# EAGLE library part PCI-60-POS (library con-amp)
PCI-SLOT 60 Dual Position 0.05 Series Standard Edge Source: http://catalog.tycoelectronics.com .. ENG_CD_145167_F.pdf
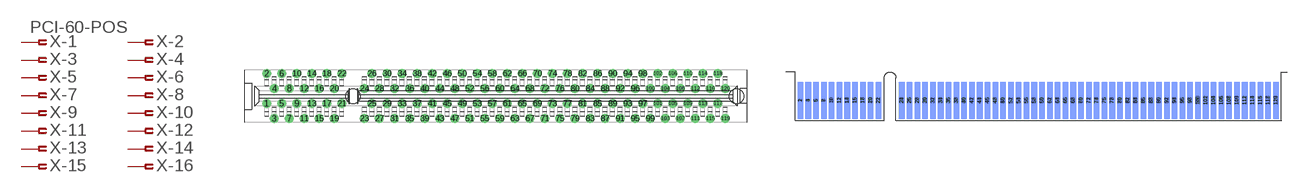
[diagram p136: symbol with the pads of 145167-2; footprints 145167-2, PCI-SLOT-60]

Designator prefix X; gates -1=PIN-FV -2=PIN-F -3=PIN-F -4=PIN-F -5=PIN-F -6=PIN-F -7=PIN-F -8=PIN-F -9=PIN-F -10=PIN-F -11=PIN-F -12=PIN-F -13=PIN-F -14=PIN-F -15=PIN-F -16=PIN-F -17=PIN-F -18=PIN-F -19=PIN-F -20=PIN-F -21=PIN-F -22=PIN-F -23=PIN-F -24=PIN-F -25=PIN-F -26=PIN-F -27=PIN-F -28=PIN-F -29=PIN-F -30=PIN-F -31=PIN-F -32=PIN-F -33=PIN-F -34=PIN-F -35=PIN-F -36=PIN-F -37=PIN-F -38=PIN-F -39=PIN-F -40=PIN-F -41=PIN-F -42=PIN-F -43=PIN-F -44=PIN-F -45=PIN-F -46=PIN-F -47=PIN-F -48=PIN-F -49=PIN-F -50=PIN-F -51=PIN-F -52=PIN-F -53=PIN-F -54=PIN-F -55=PIN-F -56=PIN-F -57=PIN-F -58=PIN-F -59=PIN-F -60=PIN-F -61=PIN-F -62=PIN-F -63=PIN-F -64=PIN-F -65=PIN-F -66=PIN-F -67=PIN-F -68=PIN-F -69=PIN-F -70=PIN-F -71=PIN-F -72=PIN-F -73=PIN-F -74=PIN-F -75=PIN-F -76=PIN-F -77=PIN-F -78=PIN-F -79=PIN-F -80=PIN-F -81=PIN-F -82=PIN-F -83=PIN-F -84=PIN-F -85=PIN-F -86=PIN-F -87=PIN-F -88=PIN-F -89=PIN-F -90=PIN-F -91=PIN-F -92=PIN-F -93=PIN-F -94=PIN-F -95=PIN-F -96=PIN-F -97=PIN-F -98=PIN-F -99=PIN-F -100=PIN-F -101=PIN-F -102=PIN-F -103=PIN-F -104=PIN-F -105=PIN-F -106=PIN-F -107=PIN-F -108=PIN-F -109=PIN-F -110=PIN-F -111=PIN-F -112=PIN-F -113=PIN-F -114=PIN-F -115=PIN-F -116=PIN-F -117=PIN-F -118=PIN-F -119=PIN-F -120=PIN-F

## PCI-60-POS-145167 (MPN: 145167-2; OC_FARNELL: unknown; OC_NEWARK: 17R3225)  [145167-2]
1  -1:1  pas
2  -2:1  pas
3  -3:1  pas
4  -4:1  pas
5  -5:1  pas
6  -6:1  pas
7  -7:1  pas
8  -8:1  pas
9  -9:1  pas
10  -10:1  pas
11  -11:1  pas
12  -12:1  pas
13  -13:1  pas
14  -14:1  pas
15  -15:1  pas
16  -16:1  pas
17  -17:1  pas
18  -18:1  pas
19  -19:1  pas
20  -20:1  pas
21  -21:1  pas
22  -22:1  pas
23  -23:1  pas
24  -24:1  pas
25  -25:1  pas
26  -26:1  pas
27  -27:1  pas
28  -28:1  pas
29  -29:1  pas
30  -30:1  pas
31  -31:1  pas
32  -32:1  pas
33  -33:1  pas
34  -34:1  pas
35  -35:1  pas
36  -36:1  pas
37  -37:1  pas
38  -38:1  pas
39  -39:1  pas
40  -40:1  pas
41  -41:1  pas
42  -42:1  pas
43  -43:1  pas
44  -44:1  pas
45  -45:1  pas
46  -46:1  pas
47  -47:1  pas
48  -48:1  pas
49  -49:1  pas
50  -50:1  pas
51  -51:1  pas
52  -52:1  pas
53  -53:1  pas
54  -54:1  pas
55  -55:1  pas
56  -56:1  pas
57  -57:1  pas
58  -58:1  pas
59  -59:1  pas
60  -60:1  pas
61  -61:1  pas
62  -62:1  pas
63  -63:1  pas
64  -64:1  pas
65  -65:1  pas
66  -66:1  pas
67  -67:1  pas
68  -68:1  pas
69  -69:1  pas
70  -70:1  pas
71  -71:1  pas
72  -72:1  pas
73  -73:1  pas
74  -74:1  pas
75  -75:1  pas
76  -76:1  pas
77  -77:1  pas
78  -78:1  pas
79  -79:1  pas
80  -80:1  pas
81  -81:1  pas
82  -82:1  pas
83  -83:1  pas
84  -84:1  pas
85  -85:1  pas
86  -86:1  pas
87  -87:1  pas
88  -88:1  pas
89  -89:1  pas
90  -90:1  pas
91  -91:1  pas
92  -92:1  pas
93  -93:1  pas
94  -94:1  pas
95  -95:1  pas
96  -96:1  pas
97  -97:1  pas
98  -98:1  pas
99  -99:1  pas
100  -100:1  pas
101  -101:1  pas
102  -102:1  pas
103  -103:1  pas
104  -104:1  pas
105  -105:1  pas
106  -106:1  pas
107  -107:1  pas
108  -108:1  pas
109  -109:1  pas
110  -110:1  pas
111  -111:1  pas
112  -112:1  pas
113  -113:1  pas
114  -114:1  pas
115  -115:1  pas
116  -116:1  pas
117  -117:1  pas
118  -118:1  pas
119  -119:1  pas
120  -120:1  pas

## PCI-60-POS-SLOT (OC_FARNELL: unknown; OC_NEWARK: unknown)  [PCI-SLOT-60]
Pads as for 145167-2

## Footprint 145167-2 (pad centres in mm)
PCI Connector 60 Dual Pos. Standard Edge .050 Series PCI Source: http://catalog.tycoelectronics.com .. ENG_CD_145167_F.pdf
drill 1 pad 1.2 round: 1 0.254,-1.27; 2 0.254,3.81; 3 1.524,-3.81; 4 1.524,1.27; 5 2.794,-1.27; 6 2.794,3.81; 7 4.064,-3.81; 8 4.064,1.27; 9 5.334,-1.27; 10 5.334,3.81; 11 6.604,-3.81; 12 6.604,1.27; 13 7.874,-1.27; 14 7.874,3.81; 15 9.144,-3.81; 16 9.144,1.27; 17 10.414,-1.27; 18 10.414,3.81; 19 11.684,-3.81; 20 11.684,1.27; 21 12.954,-1.27; 22 12.954,3.81; 23 16.764,-3.81; 24 16.764,1.27; 25 18.034,-1.27; 26 18.034,3.81; 27 19.304,-3.81; 28 19.304,1.27; 29 20.574,-1.27; 30 20.574,3.81; 31 21.844,-3.81; 32 21.844,1.27; 33 23.114,-1.27; 34 23.114,3.81; 35 24.384,-3.81; 36 24.384,1.27; 37 25.654,-1.27; 38 25.654,3.81; 39 26.924,-3.81; 40 26.924,1.27; 41 28.194,-1.27; 42 28.194,3.81; 43 29.464,-3.81; 44 29.464,1.27; 45 30.734,-1.27; 46 30.734,3.81; 47 32.004,-3.81; 48 32.004,1.27; 49 33.274,-1.27; 50 33.274,3.81; 51 34.544,-3.81; 52 34.544,1.27; 53 35.814,-1.27; 54 35.814,3.81; 55 37.084,-3.81; 56 37.084,1.27; 57 38.354,-1.27; 58 38.354,3.81; 59 39.624,-3.81; 60 39.624,1.27; 61 40.894,-1.27; 62 40.894,3.81; 63 42.164,-3.81; 64 42.164,1.27; 65 43.434,-1.27; 66 43.434,3.81; 67 44.704,-3.81; 68 44.704,1.27; 69 45.974,-1.27; 70 45.974,3.81; 71 47.244,-3.81; 72 47.244,1.27; 73 48.514,-1.27; 74 48.514,3.81; 75 49.784,-3.81; 76 49.784,1.27; 77 51.054,-1.27; 78 51.054,3.81; 79 52.324,-3.81; 80 52.324,1.27; 81 53.594,-1.27; 82 53.594,3.81; 83 54.864,-3.81; 84 54.864,1.27; 85 56.134,-1.27; 86 56.134,3.81; 87 57.404,-3.81; 88 57.404,1.27; 89 58.674,-1.27; 90 58.674,3.81; 91 59.944,-3.81; 92 59.944,1.27; 93 61.214,-1.27; 94 61.214,3.81; 95 62.484,-3.81; 96 62.484,1.27; 97 63.754,-1.27; 98 63.754,3.81; 99 65.024,-3.81; 100 65.024,1.27; 101 66.294,-1.27; 102 66.294,3.81; 103 67.564,-3.81; 104 67.564,1.27; 105 68.834,-1.27; 106 68.834,3.81; 107 70.104,-3.81; 108 70.104,1.27; 109 71.374,-1.27; 110 71.374,3.81; 111 72.644,-3.81; 112 72.644,1.27; 113 73.914,-1.27; 114 73.914,3.81; 115 75.184,-3.81; 116 75.184,1.27; 117 76.454,-1.27; 118 76.454,3.81; 119 77.724,-3.81; 120 77.724,1.27
hole 2.44 at 14.854,0
hole 2.44 at 79.624,0

## Footprint PCI-SLOT-60 (pad centres in mm)
PCI Connector 60 Dual Position 0.05 Series Standard Edge Source: http://catalog.tycoelectronics.com .. ENG_CD_145167_F.pdf
smd 0.91 x 6: 1 0,3.22; 3 1.27,3.22; 5 2.54,3.22; 7 3.81,3.22; 9 5.08,3.22; 11 6.35,3.22; 13 7.62,3.22; 15 8.89,3.22; 17 10.16,3.22; 19 11.43,3.22; 21 12.7,3.22; 23 16.51,3.22; 25 17.78,3.22; 27 19.05,3.22; 29 20.32,3.22; 31 21.59,3.22; 33 22.86,3.22; 35 24.13,3.22; 37 25.4,3.22; 39 26.67,3.22; 41 27.94,3.22; 43 29.21,3.22; 45 30.48,3.22; 47 31.75,3.22; 49 33.02,3.22; 51 34.29,3.22; 53 35.56,3.22; 55 36.83,3.22; 57 38.1,3.22; 59 39.37,3.22; 61 40.64,3.22; 63 41.91,3.22; 65 43.18,3.22; 67 44.45,3.22; 69 45.72,3.22; 71 46.99,3.22; 73 48.26,3.22; 75 49.53,3.22; 77 50.8,3.22; 79 52.07,3.22; 81 53.34,3.22; 83 54.61,3.22; 85 55.88,3.22; 87 57.15,3.22; 89 58.42,3.22; 91 59.69,3.22; 93 60.96,3.22; 95 62.23,3.22; 97 63.5,3.22; 99 64.77,3.22; 101 66.04,3.22; 103 67.31,3.22; 105 68.58,3.22; 107 69.85,3.22; 109 71.12,3.22; 111 72.39,3.22; 113 73.66,3.22; 115 74.93,3.22; 117 76.2,3.22; 119 77.47,3.22
smd 0.91 x 6 bottom: 2 0,3.22; 4 1.27,3.22; 6 2.54,3.22; 8 3.81,3.22; 10 5.08,3.22; 12 6.35,3.22; 14 7.62,3.22; 16 8.89,3.22; 18 10.16,3.22; 20 11.43,3.22; 22 12.7,3.22; 24 16.51,3.22; 26 17.78,3.22; 28 19.05,3.22; 30 20.32,3.22; 32 21.59,3.22; 34 22.86,3.22; 36 24.13,3.22; 38 25.4,3.22; 40 26.67,3.22; 42 27.94,3.22; 44 29.21,3.22; 46 30.48,3.22; 48 31.75,3.22; 50 33.02,3.22; 52 34.29,3.22; 54 35.56,3.22; 56 36.83,3.22; 58 38.1,3.22; 60 39.37,3.22; 62 40.64,3.22; 64 41.91,3.22; 66 43.18,3.22; 68 44.45,3.22; 70 45.72,3.22; 72 46.99,3.22; 74 48.26,3.22; 76 49.53,3.22; 78 50.8,3.22; 80 52.07,3.22; 82 53.34,3.22; 84 54.61,3.22; 86 55.88,3.22; 88 57.15,3.22; 90 58.42,3.22; 92 59.69,3.22; 94 60.96,3.22; 96 62.23,3.22; 98 63.5,3.22; 100 64.77,3.22; 102 66.04,3.22; 104 67.31,3.22; 106 68.58,3.22; 108 69.85,3.22; 110 71.12,3.22; 112 72.39,3.22; 114 73.66,3.22; 116 74.93,3.22; 118 76.2,3.22; 120 77.47,3.22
